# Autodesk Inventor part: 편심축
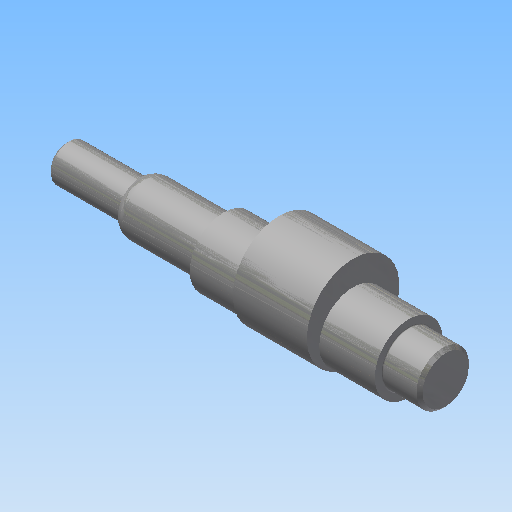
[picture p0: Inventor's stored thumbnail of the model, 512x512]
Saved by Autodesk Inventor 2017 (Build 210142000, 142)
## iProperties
Created: 2020-07
Part Number: 편심축
Material: 강철, 연강
Document SubType Name: Modeling
Designer: mduedu
Density: 7.86 g/cm^3
Mass: 329.439 g
Surface Area: 91.9334 cm^2
Volume: 41.9133 cm^3
Appearance: 강철
Author: mduedu
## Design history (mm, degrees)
sketch "스케치1"
  geometry: L1 (0, 0)-(24, 0); L2 (24, 0)-(24, 6); L3 (24, 6)-(0, 6); L4 (0, 6)-(0, 0); L5 (24, 0)-(51, 0); L6 (51, 0)-(51, 8.5); L7 (51, 8.5)-(24, 8.5); L8 (24, 8.5)-(24, 0); L9 (51, 0)-(111, 0); L10 (111, 0)-(111, 11); L11 (111, 11)-(51, 11); L12 (51, 11)-(51, 0); L13 (111, 0)-(123, 0); L14 (123, 0)-(123, 8.5); L15 (123, 8.5)-(111, 8.5); L16 (111, 8.5)-(111, 0)
  constraints: 32 end point, 8 parallel, 4 horizontal, 4 perpendicular
  dimensions: "d0" = 123 distance between parallel lines of L14 L4; "d2" = 12 distance of L14.end L15.end; "d3" = 60 distance of L10.end L11.end; "d4" = 99 distance between parallel lines of L8 L14; "d5" = 24 distance of L2.end L3.end (derived); "d6" = 12 diameter of L3 L1; "d7" = 17 diameter of L7 L5; "d8" = 22 diameter of L11 L9; "d9" = 17 diameter of L15 L13
revolve "회전1" sketch "스케치1" stored, may be unused: angle "d10" = 90 deg
node "작업 평면1"
sketch "스케치2"
  geometry: C1 r 15 at (-4, 0); C2 r 11 at (0, 0) reference; 1 further point
  constraints: 1 centre point, 1 horizontal alignment, 1 tangent
  dimensions: "d12" = 4 distance of point (0, 0) C1.centre
extrude "돌출1" join sketch "스케치2" distance "d13" = 24; taper "d14" = 0 deg
node "작업 평면2"
sketch "스케치3" dims "d17" = 12
  geometry: L1 (5, -2)-(-3, -2); L2 (-3, -2)-(-3, 2); L3 (-3, 2)-(5, 2); L4 (5, 2)-(5, -2); L5 (-12, 8.5)-(-12, -8.5); L6 (-12, 8.5)-(-12, -8.5) reference; L7 (12, 6)-(12, -6) reference; 5 further points
  constraints: 10 end point, 4 midpoint, 2 horizontal alignment, 2 parallel, 2 vertical alignment, 1 coincident, 1 collinear, 1 horizontal, 1 perpendicular, 4 other
  dimensions: "d15" = 7 dimension on L5; "d16" = 4 distance between parallel lines of L3 L1
extrude "돌출2" cut sketch "스케치3" distance "d18" = 2.5; taper "d19" = 0 deg
hole "구멍1" diameter "d22" = 3.242; stored, may be unused: countersink angle "d26" = 90 deg, drill point angle "d28" = 118 deg; dims "d20" = 10, "d21" = 10, "d23" = 8, "d24" = 4, "d25" = 2, "d27" = 10
sketch "스케치4"
  geometry: L1 (10, 1.621)-(0, 1.621) reference; L2 (0, 0)-(2, 0); L3 (2, 0)-(2, 1.621); L4 (0, 2.776)-(0, 0); L5 (0, 2.776)-(2, 1.621)
  constraints: 8 end point, 1 horizontal, 1 parallel, 1 perpendicular, 1 point on line
  dimensions: "d29" = 2 horizontal distance of L4.start L3.end; "d31" = 30 deg angle of L5 L2
revolve "회전2" sketch "스케치4" stored, may be unused: angle "d33" = 90 deg
chamfer "모따기1" distance "d34" = 1; stored, may be unused: second distance "d35" = 2, angle "d36" = 45 deg
fillet "모깎기1" dims "d37" = 0.3
sketch "스케치5"
  geometry: L1 (24, -8.5)-(24, 8.5) reference; L2 (24, 8.5)-(50.7, 8.5) reference; L3 (24, 7.45)-(25.819, 8.5); L4 (0, 0)-(24, 0)
  constraints: 4 end point, 2 point on line, 1 midpoint
  dimensions: "d38" = 14.9 diameter of L3.start L4; "d39" = 30 deg angle of L3 L2
revolve "회전3" sketch "스케치5" stored, may be unused: angle "d40" = 90 deg
fillet "모깎기2" dims "d41" = 4, "d42" = 0.5
node "솔리드1"
